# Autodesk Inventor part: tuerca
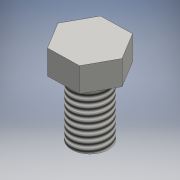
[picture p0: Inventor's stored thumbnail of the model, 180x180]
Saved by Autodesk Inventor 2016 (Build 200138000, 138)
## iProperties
Created: 2016-06
Part Number: tuerca
Material: Generic
Document SubType Name: Modeling
Designer: yesi alvarez
Mass: 0.0698631 g
Surface Area: 1.12574 cm^2
Volume: 0.0698631 cm^3
Density: 1 g/cm^3
Appearance: Default
Author: yesi alvarez
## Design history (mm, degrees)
sketch "Sketch1"
  geometry: C1 r 1.5 at (0, 0); 1 further point
  constraints: 1 centre point, 1 coincident
  dimensions: "d0" = 3 diameter of C1
extrude "Extrusion1" new body sketch "Sketch1" distance "d1" = 5; taper "d2" = 0 deg
sketch "Sketch2"
  geometry: L1 (1.241, 2.259)-(2.577, 0.055); L2 (2.577, 0.055)-(1.336, -2.204); L3 (1.336, -2.204)-(-1.241, -2.259); L4 (-1.241, -2.259)-(-2.577, -0.055); L5 (-2.577, -0.055)-(-1.336, 2.204); L6 (-1.336, 2.204)-(1.241, 2.259); 2 further points
  constraints: 12 end point, 1 coincident, 13 other
extrude "Extrusion2" join sketch "Sketch2" distance "d3" = 2; taper "d4" = 0 deg
thread "Thread1" dims "d5" = 10, "d6" = 0
body "Solid1"
